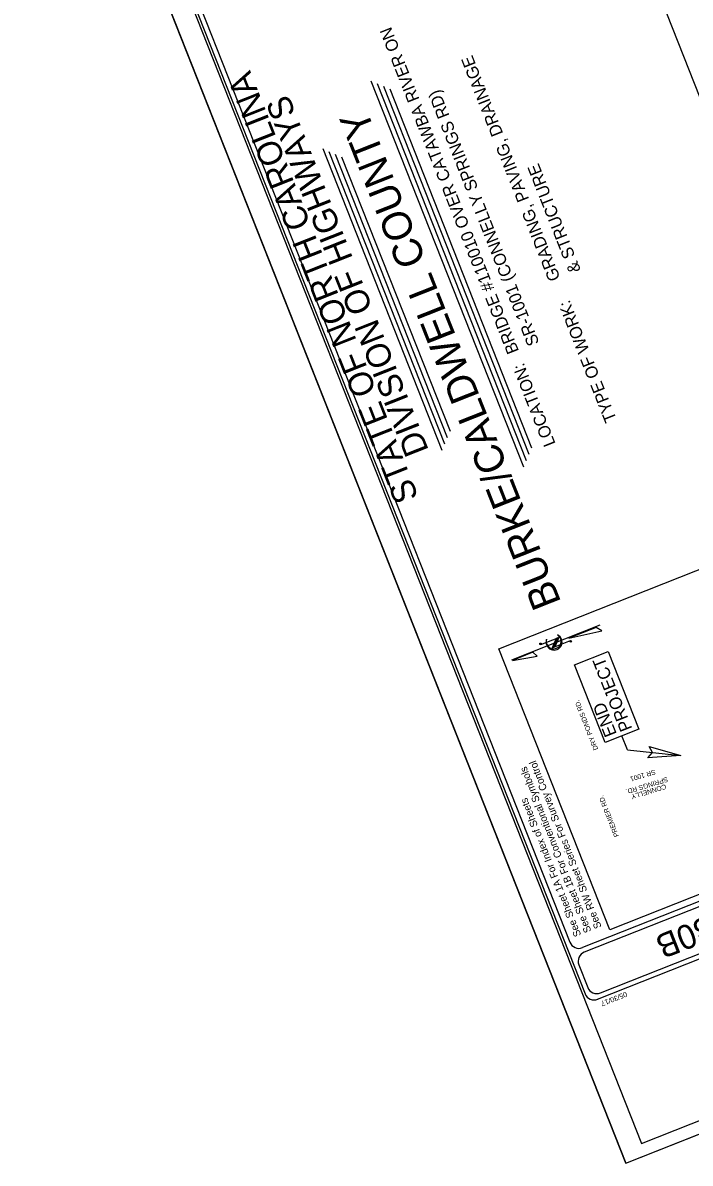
# Model space of a CAD drawing. Extents: x 1247235 to 1260080, y 742320 to 754020.
# Drawn here: x 1247235 to 1250319, y 742966 to 748232 of the extents above; entities that cross this region are included whole.
import ezdxf

# ---------------------------------------------------------------- set-up
doc = ezdxf.new("R2010")
doc.units = 0
for name, color, linetype in [('Prop DSN Text', 7, 'Continuous'), ('Prop Grid Mask', 7, 'Continuous'), ('Prop Terminator CELL', 7, 'Continuous'), ('Scratch_Level_0', 7, 'Continuous'), ('Scratch_Level_3', 7, 'Continuous'), ('Sheet Cutting Line CELL', 7, 'Continuous'), ('Sheet Data Field CELL', 7, 'Continuous'), ('Sheet North Arrow CELL', 7, 'Continuous'), ('Sheet Plot Border Inside CELL', 7, 'Continuous'), ('Sheet Plot Border Outside CELL', 7, 'Continuous'), ('Sheet Title CELL', 7, 'Continuous'), ('Sheet Title Data Points CELL', 7, 'Continuous')]:
    doc.layers.add(name, color=color, linetype=linetype)

msp = doc.modelspace()

# ---------------------------------------------------------------- linework, layer by layer
at = {"layer": 'Prop DSN Text'}
for q in [(1250003.7, 744938.8), (1250276.1, 744848.5)]:
    msp.add_line((1250028.9, 744875.1), q, dxfattribs=at)
at = {"layer": 'Prop Grid Mask'}
msp.add_lwpolyline([(1249925.7, 744908), (1249783.9, 745266.6), (1249939.9, 745328.2), (1250081.7, 744969.6)], close=True, dxfattribs=at)
at = {"layer": 'Prop Terminator CELL'}
msp.add_lwpolyline([(1250129.2, 744890.3), (1250276.1, 744848.5), (1250122.7, 744838), (1250144.7, 744862.6)], close=True, dxfattribs=at)
at = {"layer": 'Scratch_Level_0'}
msp.add_lwpolyline([(1249947.5, 744043.6), (1249434.6, 745340.9), (1250878.3, 745911.7), (1251391.3, 744614.5)], close=True, dxfattribs=at)
at = {"layer": 'Scratch_Level_3'}
msp.add_lwpolyline([(1251095.3, 746040.1), (1249533.8, 749989.2), (1251115.9, 750614.8), (1252677.6, 746665.7)], close=True, dxfattribs=at)
at = {"layer": 'Sheet Cutting Line CELL'}
for q in [(1247234.8, 750013.1), (1254624.4, 744786.1)]:
    msp.add_line((1250021.3, 742966), q, dxfattribs=at)
at = {"layer": 'Sheet North Arrow CELL'}
for p, q in [((1249900.6, 745450.5), (1249492.6, 745289.2)), ((1249628.5, 745360.7), (1249712.2, 745393.8)), ((1249655.1, 745384.6), (1249655.3, 745385.2)), ((1249699.2, 745388.7), (1249680.3, 745345.1)), ((1249680.3, 745345.1), (1249765.4, 745378.8)), ((1249702.2, 745389.9), (1249683.4, 745346.4)), ((1249709.9, 745392.9), (1249691, 745349.4)), ((1249691, 745349.4), (1249709.9, 745392.9)), ((1249712.2, 745393.8), (1249693.4, 745350.3)), ((1249709.9, 745392.9), (1249702.2, 745389.9)), ((1249683.4, 745346.4), (1249691, 745349.4))]:
    msp.add_line(p, q, dxfattribs=at)
for points in [[(1249758.2, 745390.4), (1249911, 745424.1), (1249883.7, 745440)], [(1249497.3, 745287.8), (1249612.4, 745306.4), (1249591.4, 745325)]]:
    msp.add_lwpolyline(points, close=True, dxfattribs=at)
for centre in [(1249627.2, 745364.1), (1249766.9, 745375.5)]:
    msp.add_circle(centre, 3.58, dxfattribs=at)
for centre, radius, start, end in [((1249689.8, 745372.2), 36.9, 159.4144, 63.9684), ((1249688.4, 745375.5), 34.5, 164.6694, 60.2031)]:
    msp.add_arc(centre, radius, start, end, dxfattribs=at)
at = {"layer": 'Sheet Plot Border Inside CELL'}
msp.add_lwpolyline([(1254509, 744803.4), (1251751.5, 751777.2), (1247336.2, 750031.4), (1250093.7, 743057.5)], close=True, dxfattribs=at)
at = {"layer": 'Sheet Plot Border Outside CELL'}
msp.add_lwpolyline([(1247234.8, 750013.1), (1250021.3, 742966), (1254624.4, 744786.1), (1251837.9, 751833.2)], close=True, dxfattribs=at)
at = {"layer": 'Sheet Title CELL'}
for p, q in [((1249549.5, 746180), (1248844.6, 747962.8)), ((1249562.1, 746209.2), (1248873.8, 747950.1)), ((1249574.8, 746238.4), (1248903, 747937.4)), ((1249587.4, 746267.6), (1248932.2, 747924.8)), ((1249172.7, 746256.8), (1248622.1, 747649.2)), ((1249185.3, 746286), (1248651.3, 747636.6)), ((1249198, 746315.2), (1248680.5, 747623.9)), ((1249210.7, 746344.4), (1248709.7, 747611.3)), ((1254098, 745628), (1249829.6, 743940.2)), ((1253315.5, 745342.8), (1249821.3, 743961.2))]:
    msp.add_line(p, q, dxfattribs=at)
for points in [[(1247384.1, 749941.4), (1249832.9, 743748)], [(1247413.3, 749928.8), (1249762.9, 743986.5)], [(1249891.3, 743722.7), (1254201.7, 745427.1)], [(1249891.3, 743722.7), (1254201.6, 745427)], [(1249904, 743752), (1254172.4, 745439.7)], [(1249804.3, 743881.9), (1249845.6, 743777.3)]]:
    msp.add_lwpolyline(points, dxfattribs=at)
msp.add_lwpolyline([(1249947.5, 744043.6), (1249434.6, 745340.9), (1250878.3, 745911.7), (1251391.3, 744614.5)], close=True, dxfattribs=at)
for centre, start, end in [((1249804.8, 744003), 201.5743, 291.5743), ((1249846.1, 743898.4), 111.5743, 201.5457), ((1249887.4, 743793.8), 201.5457, 291.5736), ((1249874.8, 743764.6), 201.5739, 291.5743)]:
    msp.add_arc(centre, 45, start, end, dxfattribs=at)
at = {"layer": 'Sheet Title Data Points CELL'}
for p, q in [((1249161, 747645.5), (1249161, 747645.5)), ((1249132.1, 747053.2), (1249132.1, 747053.2))]:
    msp.add_line(p, q, dxfattribs=at)

# ---------------------------------------------------------------- texts
at = {"layer": 'Prop DSN Text'}
for s, p in [('PROJECT', (1250052.3, 744972.9)), ('END ', (1249980.7, 744948.2))]:
    msp.add_text(s, height=57.69, rotation=111.5743, dxfattribs=at).set_placement(p)
at = {"layer": 'Sheet Data Field CELL'}
for s, height, rotation, p in [('BRIDGE #110010 OVER CATAWBA RIVER ON ', 56.25, 111.5743, (1249528.5, 746716)), ('GRADING, PAVING, DRAINAGE               ', 56.25, 111.5743, (1249720, 747052)), ('SR-1001 (CONNELLY SPRINGS RD)', 56.25, 111.5743, (1249622.6, 746753.2)), ('    BURKE/CALDWELL COUNTY    ', 135, 111.5743, (1249798, 745369.2)), ('& STRUCTURE                             ', 56.25, 111.5743, (1249814.2, 747089.3)), ('DRY PONDS RD.', 22.5, 111.3653, (1249894.3, 744877.9)), ('SR 1001', 22.5, 196.921, (1250154.7, 744784.3)), ('SPRINGS RD.', 22.5, 196.921, (1250211.9, 744749.5)), ('CONNELLY', 22.5, 196.921, (1250204.4, 744716.6)), ('PREMIER RD.', 22.5, 111.3653, (1249990.1, 744477.2))]:
    msp.add_text(s, height=height, rotation=rotation, dxfattribs=at).set_placement(p)
at = {"layer": 'Sheet Title CELL'}
for s, height, rotation, p in [('STATE OF NORTH CAROLINA', 112.5, 111.5743, (1249064.8, 746040.9)), ('DIVISION OF HIGHWAYS', 112.5, 111.5743, (1249112.1, 746257.5)), ('TYPE OF WORK:', 56.25, 111.5743, (1249980.2, 746399.7)), ('LOCATION: ', 56.25, 111.5743, (1249697.7, 746288)), ('See Sheet 1B For Conventional Symbols', 33.75, 111.5743, (1249863, 744037.6)), ('See RW Sheet Series For Survey Control', 33.75, 111.5743, (1249910.1, 744056.2)), ('See Sheet 1A For Index of Sheets', 33.75, 111.5743, (1249816, 744019)), ('R-3430B ', 112.5, 201.5743, (1250701.8, 744230)), ('05/30/17', 23.62, 201.5743, (1250021.9, 743758.6))]:
    msp.add_text(s, height=height, rotation=rotation, dxfattribs=at).set_placement(p)

doc.saveas('drawing.dxf')
